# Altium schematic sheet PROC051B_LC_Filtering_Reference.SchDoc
size 431 x 279 mm; Date: Not shown in title block; ApprovedBy: Not shown in title block; CheckedBy: Not shown in title block; Author: Not shown in title block; CompanyName: Not shown in title block; Engineer: Not shown in title block; Organization: Not shown in title block; Address1: Not shown in title block; Address2: Not shown in title block; Address3: Not shown in title block; Address4: Not shown in title block; DocumentNumber: 5; Revision: Use project parameter SCH_Rev; SheetNumber: 5; SheetTotal: 16; PageSetup: Record=PageOptions¦CenterHorizontal=True¦CenterVertical=True¦PrintScale=1.00¦XCorrection=1.00¦YCorrection=1.00¦PrintKind=0¦BorderSize=5000000¦LeftOffset=0¦BottomOffset=0¦Orientation=2¦PaperLength=1000¦PaperWidth=1000¦Scale=100¦PaperSource=15¦PrintQuality=600¦MediaType=1¦DitherType=10¦PaperKind=Letter¦PrintScaleMode=1
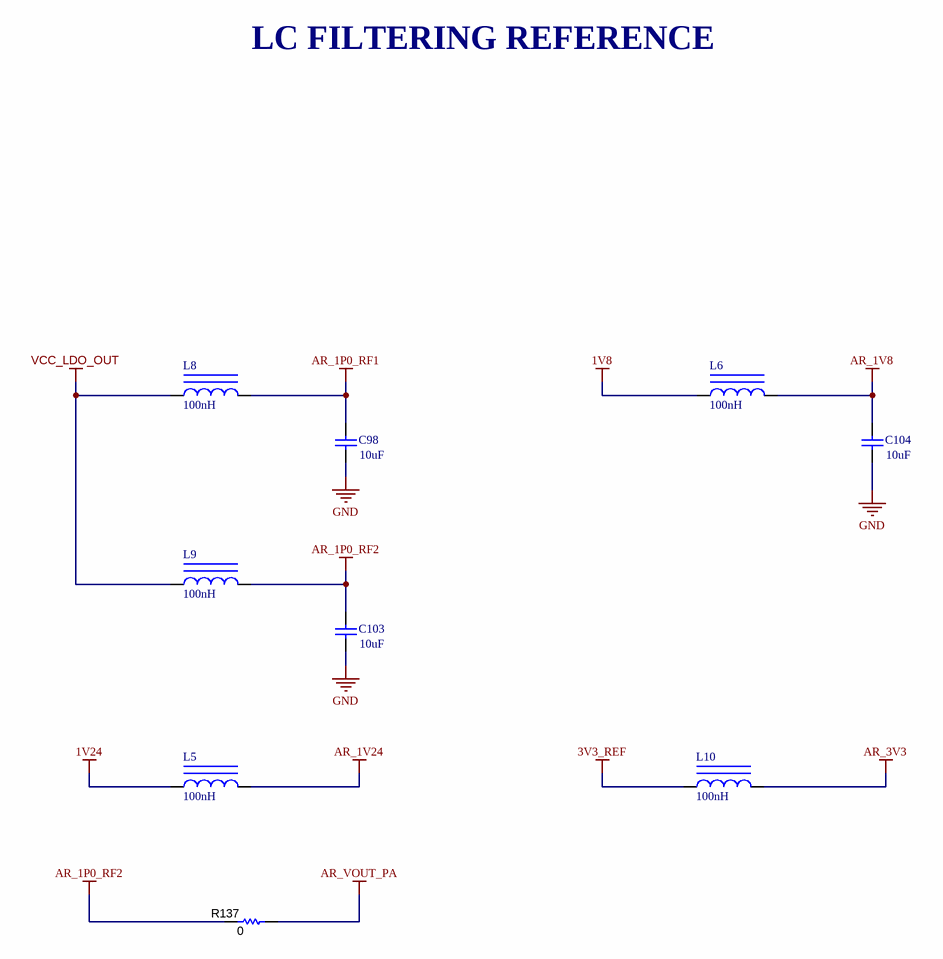
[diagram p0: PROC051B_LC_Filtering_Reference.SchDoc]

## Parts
C98  ValueDisplayed: 10uF  [0805_HV]  (hidden comment: GCM21BR71A106KE22L)
C103  ValueDisplayed: 10uF  [0805_HV]  (hidden comment: GCM21BR71A106KE22L)
C104  ValueDisplayed: 10uF  [0805_HV]  (hidden comment: GCM21BR71A106KE22L)
L5  ValueDisplayed: 100nH  [NLCV32]  (hidden comment: NLCV32T-R10M-EFRD)
L6  ValueDisplayed: 100nH  [NLCV32]  (hidden comment: NLCV32T-R10M-EFRD)
L8  ValueDisplayed: 100nH  [NLCV32]  (hidden comment: NLCV32T-R10M-EFRD)
L9  ValueDisplayed: 100nH  [NLCV32]  (hidden comment: NLCV32T-R10M-EFRD)
L10  ValueDisplayed: 100nH  [NLCV32]  (hidden comment: NLCV32T-R10M-EFRD)
R137  ValueDisplayed: 0  [0603]  (hidden comment: MCT06030Z0000ZP500)

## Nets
1V8: L6.1
1V24: L5.1
3V3_REF: L10.1
AR_1P0_RF1: C98.1 L8.2
AR_1P0_RF2: C103.1 L9.2 R137.1
AR_1V8: C104.1 L6.2
AR_1V24: L5.2
AR_3V3: L10.2
AR_VOUT_PA: R137.2
GND: C98.2 C103.2 C104.2
VCC_LDO_OUT: L8.1 L9.1

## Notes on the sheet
- LC FILTERING REFERENCE

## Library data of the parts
C98 C103 C104 = CMP-0008017-2: CAP, CERM, 10 uF, 10 V, +/- 10%, X7R, 0805; Manufacturer: MuRata; TaMin_C: -55°C; Polarized: N; SizeAreaWB_mm2: 6.75; Value1: Unknown; U/M: EA; Value: 10uF; TaMax_C: 125°C; SizeZ_mm: 1.45; SizeX_mm: 2; SizeY_mm: 1.25; Cap_Case: 0805; Value2: 10V; SizeArea_mm2: 2.5; Cap_F: 10µF; AEC Category: Q200
L5 L6 L8-L10 = CMP-0083745-1: Inductor, Wirewound, Ferrite, 100 nH, 2.85 A, 0.024 ohm, AEC-Q200 Grade 1, SMD; Manufacturer: TDK; Isat: 2.85A @ 10% inductance drop; Irms: 2.85A @ 40C rise; SizeAreaWB_mm2: 13.44; DCR_ohm: 0.024; Value: 100nH; Imax_A: 2.85A; SizeZ_mm: 2.5; SizeX_mm: 3.2; SizeY_mm: 2.2; SizeArea_mm2: 7.04; AEC Qualified: Y; AEC Grade: 1; AEC Category: Q200
R137 = CMP-0025884-3: RES, 0, 5%, 0.125 W, 0603; Manufacturer: Vishay/Beyschlag; Power_W: 125mW; TempCo: ppm/C; Value_Code: 0000; U/M: EA; Value: 0; EIA_Code: E24; SizeX_mm: 1.6; SizeY_mm: 0.8; SizeZ_mm: 1; Value2: 0.125W; SizeArea_mm2: 1.28; CompType: Resistor; AEC Qualified: N; AEC Category: Q200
